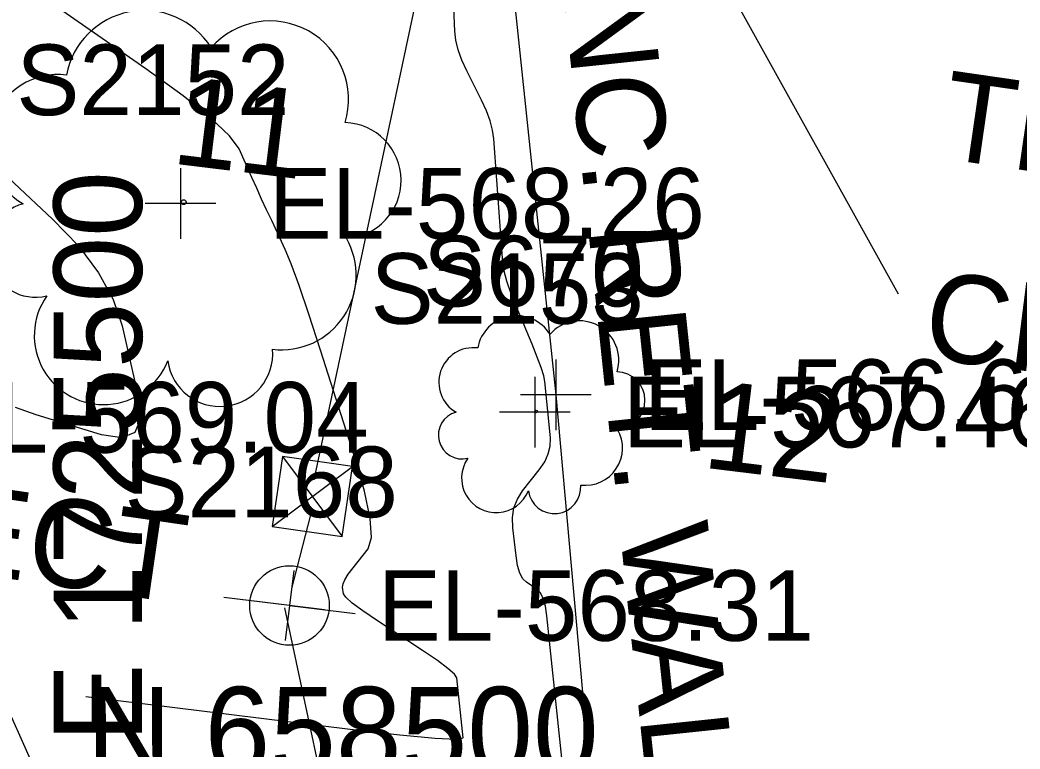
# Model space of a CAD drawing. Extents: x 1724534 to 1727318, y 657156 to 660047.
# Drawn here: x 1725500.6 to 1725557.2, y 658504 to 658545.3 of the extents above; entities that cross this region are included whole.
import ezdxf

# ---------------------------------------------------------------- set-up
doc = ezdxf.new("R2010")
doc.units = 0
for name, color, linetype in [('SURVEY - CONTOURS - Intermediate with optional Text', 7, 'Continuous'), ('SURVEY - CONTROL - Grid Text', 7, 'Continuous'), ('SURVEY - DRAINAGE - Storm Sewer', 7, 'Continuous'), ('SURVEY - NON-TRANSPORTATION - Features - Points - Elevations', 7, 'Continuous'), ('SURVEY - NON-TRANSPORTATION - Features - Points - Locators', 7, 'Continuous'), ('SURVEY - NON-TRANSPORTATION - Features - Points - Numbers', 7, 'Continuous'), ('SURVEY - NON-TRANSPORTATION - Features Text', 7, 'Continuous'), ('SURVEY - ROADSIDE BARRIERS with Text', 7, 'Continuous'), ('SURVEY - UTILITIES - Electric (Underground) with Text', 7, 'Continuous'), ('SURVEY - UTILITIES - Poles and Miscellaneous - Points - Elevations', 7, 'Continuous'), ('SURVEY - UTILITIES - Poles and Miscellaneous - Points - Locators', 7, 'Continuous'), ('SURVEY - UTILITIES - Poles and Miscellaneous - Points - Numbers', 7, 'Continuous'), ('SURVEY - UTILITIES - Poles and Miscellaneous with Text', 7, 'Continuous'), ('SURVEY - VEGETATION - Features - Points - Elevations', 7, 'Continuous'), ('SURVEY - VEGETATION - Features - Points - Locators', 7, 'Continuous'), ('SURVEY - VEGETATION - Features - Points - Numbers', 7, 'Continuous'), ('SURVEY - VEGETATION - Features with Text', 7, 'Continuous')]:
    doc.layers.add(name, color=color, linetype=linetype)

msp = doc.modelspace()

# ---------------------------------------------------------------- linework, layer by layer
at = {"layer": 'SURVEY - CONTOURS - Intermediate with optional Text'}
for points in [[(1725504.324, 658506.95), (1725519.298, 658505.111), (1725522.104, 658504.785), (1725524.104, 658504.594), (1725525.297, 658504.539), (1725525.685, 658504.62), (1725525.328, 658508.005), (1725525.195, 658508.212), (1725524.827, 658508.54), (1725524.225, 658508.988), (1725523.389, 658509.556), (1725520.845, 658511.232), (1725520.008, 658511.8), (1725519.406, 658512.247), (1725519.038, 658512.572), (1725518.904, 658512.775), (1725518.859, 658513.155), (1725518.884, 658513.33), (1725518.992, 658513.57), (1725519.184, 658513.875), (1725519.46, 658514.245), (1725520.307, 658515.319), (1725520.496, 658515.951), (1725520.427, 658517.041), (1725520.101, 658518.591), (1725519.517, 658520.599), (1725517.615, 658526.567), (1725516.955, 658528.602), (1725516.401, 658530.23), (1725515.954, 658531.452), (1725515.613, 658532.268), (1725514.845, 658533.903), (1725514.559, 658534.515), (1725514.277, 658535.127), (1725513.999, 658535.737), (1725513.725, 658536.347), (1725512.999, 658537.972), (1725512.465, 658538.712), (1725511.408, 658539.713), (1725509.826, 658540.974), (1725507.721, 658542.496), (1725501.409, 658546.904)], [(1725531.902, 658497.562), (1725530.429, 658511.528), (1725530.345, 658512.076), (1725530.222, 658512.509), (1725530.059, 658512.827), (1725529.857, 658513.031), (1725529.265, 658513.421), (1725529.061, 658513.624), (1725528.896, 658513.94), (1725528.768, 658514.37), (1725528.678, 658514.912), (1725528.489, 658516.51), (1725528.471, 658517.091), (1725528.559, 658517.633), (1725528.753, 658518.138), (1725529.054, 658518.605), (1725529.997, 658519.799), (1725530.301, 658520.247), (1725530.506, 658520.692), (1725530.613, 658521.135), (1725530.621, 658521.577), (1725530.404, 658523.86), (1725530.311, 658524.803), (1725530.247, 658525.123), (1725530.105, 658525.582), (1725529.883, 658526.18), (1725529.583, 658526.916), (1725528.678, 658529.066), (1725528.377, 658529.823), (1725528.153, 658530.482), (1725528.007, 658531.043), (1725527.937, 658531.506), (1725527.419, 658538.54), (1725527.35, 658539.026), (1725527.211, 658539.552), (1725527.002, 658540.118), (1725526.725, 658540.723), (1725525.891, 658542.39), (1725525.614, 658542.999), (1725525.411, 658543.575), (1725525.28, 658544.119), (1725525.222, 658544.63), (1725525.166, 658545.95)], [(1725498.074, 658538.058), (1725502.428, 658533.992), (1725503.9, 658532.471), (1725505.048, 658530.955), (1725505.873, 658529.446), (1725506.376, 658527.942), (1725507.285, 658523.94), (1725507.411, 658522.68), (1725507.106, 658521.899), (1725506.371, 658521.599), (1725505.204, 658521.779), (1725501.52, 658522.898), (1725500.336, 658523.319)]]:
    msp.add_lwpolyline(points, dxfattribs=at)
at = {"layer": 'SURVEY - DRAINAGE - Storm Sewer'}
msp.add_line((1725462.985, 658588.87), (1725518.528, 658464.57), dxfattribs=at)
at = {"layer": 'SURVEY - NON-TRANSPORTATION - Features - Points - Locators'}
for p, q in [((1725530.925, 658526.045), (1725530.925, 658522.045)), ((1725532.925, 658524.045), (1725528.925, 658524.045))]:
    msp.add_line(p, q, dxfattribs=at)
at = {"layer": 'SURVEY - NON-TRANSPORTATION - Features Text'}
msp.add_line((1725532.926, 658561.059), (1725550.309, 658529.751), dxfattribs=at)
at = {"layer": 'SURVEY - ROADSIDE BARRIERS with Text'}
msp.add_lwpolyline([(1725527.49, 658556.696), (1725530.925, 658524.045), (1725533.591, 658494.365)], dxfattribs=at)
at = {"layer": 'SURVEY - UTILITIES - Electric (Underground) with Text'}
for p, q in [((1725526.157, 658561.177), (1725517.229, 658519.229)), ((1725517.042, 658517.251), (1725515.965, 658513.062))]:
    msp.add_line(p, q, dxfattribs=at)
at = {"layer": 'SURVEY - UTILITIES - Poles and Miscellaneous - Points - Locators'}
for p, q in [((1725516.097, 658514.093), (1725515.611, 658510.123)), ((1725517.839, 658511.865), (1725513.869, 658512.351))]:
    msp.add_line(p, q, dxfattribs=at)
at = {"layer": 'SURVEY - UTILITIES - Poles and Miscellaneous with Text'}
for p, q in [((1725515.454, 658520.547), (1725518.838, 658516.015)), ((1725514.88, 658516.589), (1725519.412, 658519.973)), ((1725517.146, 658518.281), (1725517.146, 658518.281)), ((1725515.854, 658512.108), (1725512.132, 658512.563)), ((1725515.566, 658511.974), (1725517.911, 658501.053)), ((1725515.854, 658512.108), (1725519.576, 658511.653))]:
    msp.add_line(p, q, dxfattribs=at)
msp.add_lwpolyline([(1725515.454, 658520.547), (1725514.88, 658516.589), (1725518.838, 658516.015), (1725519.412, 658519.973), (1725515.454, 658520.547)], dxfattribs=at)
msp.add_circle((1725515.854, 658512.108), 2.25, dxfattribs=at)
at = {"layer": 'SURVEY - VEGETATION - Features - Points - Locators'}
for p, q in [((1725509.68, 658536.878), (1725509.68, 658532.878)), ((1725511.68, 658534.878), (1725507.68, 658534.878)), ((1725529.734, 658525.061), (1725529.734, 658521.061)), ((1725531.734, 658523.061), (1725527.734, 658523.061))]:
    msp.add_line(p, q, dxfattribs=at)
at = {"layer": 'SURVEY - VEGETATION - Features with Text'}
for centre, radius in [((1725509.864, 658534.95), 0.137), ((1725529.826, 658523.097), 0.0685)]:
    msp.add_circle(centre, radius, dxfattribs=at)
for centre, radius, start, end in [((1725507.625, 658541.33), 4.472, 31.9683, 169.4925), ((1725514.756, 658540.766), 4.443, 342.8641, 138.7026), ((1725502.753, 658538.251), 3.925, 82.9155, 239.7044), ((1725518.895, 658536.181), 3.277, 273.117, 88.1173), ((1725501.472, 658532.26), 2.694, 105.0317, 283.7773), ((1725515.408, 658530.811), 4.223, 262.9581, 29.8037), ((1725505.324, 658527.4), 3.917, 145.0523, 338.472), ((1725528.706, 658526.287), 2.236, 31.9683, 169.4925), ((1725532.272, 658526.005), 2.222, 342.8641, 138.7026), ((1725511.921, 658526.36), 2.981, 187.671, 4.9902), ((1725526.27, 658524.747), 1.962, 82.9155, 239.7044), ((1725534.341, 658523.713), 1.638, 273.117, 88.1173), ((1725525.63, 658521.752), 1.347, 105.0317, 283.7773), ((1725532.598, 658521.027), 2.111, 262.9581, 29.8037), ((1725527.556, 658519.322), 1.958, 145.0523, 338.472), ((1725530.855, 658518.802), 1.49, 187.671, 4.9902)]:
    msp.add_arc(centre, radius, start, end, dxfattribs=at)

# ---------------------------------------------------------------- texts
at = {"layer": 'SURVEY - CONTROL - Grid Text'}
msp.add_text(' E 1725500 ', height=5, rotation=90, dxfattribs=at).set_placement((1725507.5, 658502.5))
msp.add_text(' N 658500 ', height=5, dxfattribs=at).set_placement((1725502.5, 658502.5))
at = {"layer": 'SURVEY - NON-TRANSPORTATION - Features - Points - Elevations'}
msp.add_text('EL-566.67', height=4, dxfattribs=at).set_placement((1725535.925, 658522.045))
at = {"layer": 'SURVEY - NON-TRANSPORTATION - Features - Points - Numbers'}
msp.add_text('S670', height=4, dxfattribs=at).set_placement((1725523.416, 658529.045))
at = {"layer": 'SURVEY - NON-TRANSPORTATION - Features Text'}
msp.add_text('CHAINLINK', height=5, rotation=352.8338, dxfattribs=at).set_placement((1725551.603, 658526.133))
at = {"layer": 'SURVEY - ROADSIDE BARRIERS with Text'}
msp.add_text('CONC. RET. WALL', height=5, rotation=276.0056, dxfattribs=at).set_placement((1725530.304, 658556.776))
at = {"layer": 'SURVEY - UTILITIES - Poles and Miscellaneous - Points - Elevations'}
for s, p in [('EL-569.04', (1725495.651, 658520.766)), ('EL-569.04', (1725495.651, 658520.766)), ('EL-568.31', (1725520.854, 658510.108))]:
    msp.add_text(s, height=4, dxfattribs=at).set_placement(p)
at = {"layer": 'SURVEY - UTILITIES - Poles and Miscellaneous - Points - Numbers'}
msp.add_text('S2168', height=4, dxfattribs=at).set_placement((1725506.519, 658517.108))
at = {"layer": 'SURVEY - UTILITIES - Poles and Miscellaneous with Text'}
for s, p in [('TDOT ITS', (1725552.565, 658537.463)), ('ELECT', (1725488.28, 658515.314))]:
    msp.add_text(s, height=5, rotation=351.7546, dxfattribs=at).set_placement(p)
at = {"layer": 'SURVEY - VEGETATION - Features - Points - Elevations'}
for s, p in [('EL-568.26', (1725514.68, 658532.878)), ('EL-567.46', (1725534.734, 658521.061))]:
    msp.add_text(s, height=4, dxfattribs=at).set_placement(p)
at = {"layer": 'SURVEY - VEGETATION - Features - Points - Numbers'}
for s, p in [('S2152', (1725500.392, 658539.878)), ('S2153', (1725520.446, 658528.061))]:
    msp.add_text(s, height=4, dxfattribs=at).set_placement(p)
at = {"layer": 'SURVEY - VEGETATION - Features with Text'}
for s, p in [('11', (1725509.104, 658537.152)), ('12', (1725539.161, 658519.931))]:
    msp.add_text(s, height=5, rotation=353.0264, dxfattribs=at).set_placement(p)

doc.saveas('drawing.dxf')
